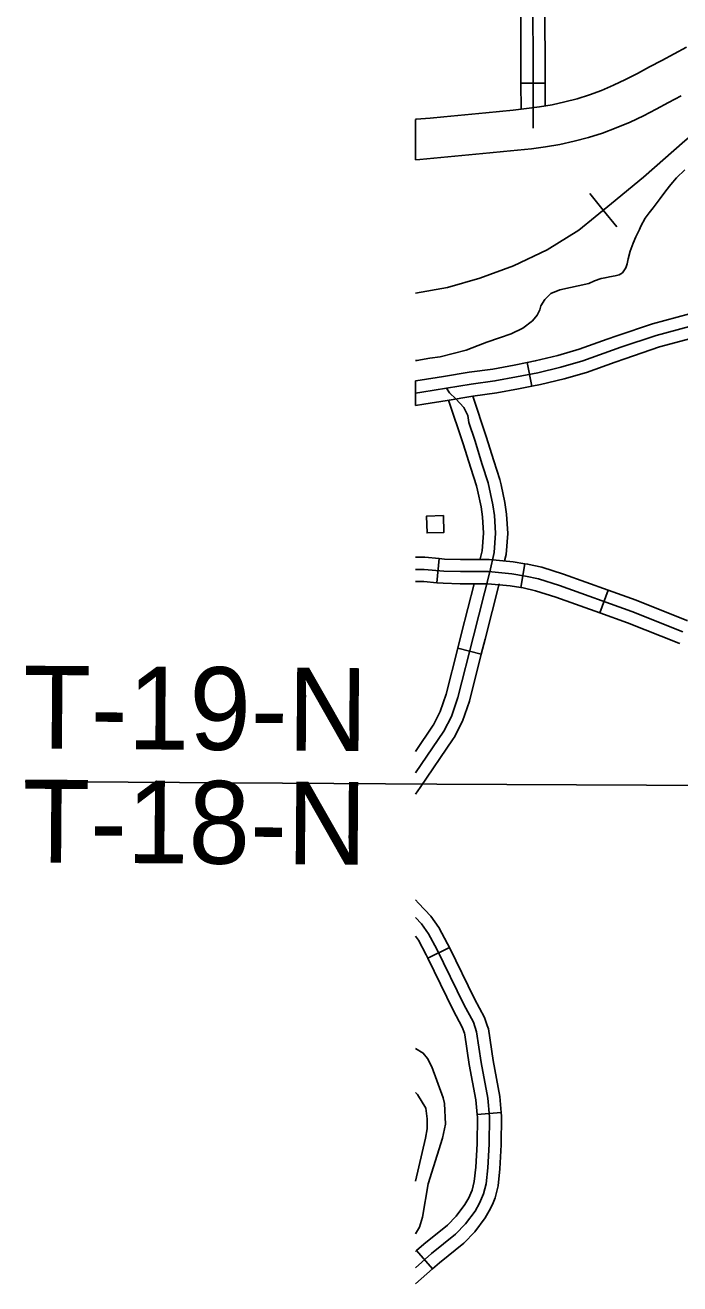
# Model space of a CAD drawing. Extents: x 1370130 to 1380143, y 377636 to 380256.
# Drawn here: x 1377941.5 to 1378111.8, y 378135.3 to 378462.7 of the extents above; entities that cross this region are included whole.
import ezdxf

# ---------------------------------------------------------------- set-up
doc = ezdxf.new("R2010")
doc.units = 0
for name, color, linetype in [('Level 15', 7, 'Continuous'), ('Level 31', 7, 'Continuous'), ('Level 32', 7, 'Continuous'), ('Level 35', 7, 'Continuous'), ('Level 4', 7, 'Continuous'), ('Level 40', 7, 'Continuous'), ('Level 45', 7, 'Continuous'), ('Level 5', 7, 'Continuous'), ('Level 56', 7, 'Continuous'), ('R_Draft', 7, 'Continuous')]:
    doc.layers.add(name, color=color, linetype=linetype)

msp = doc.modelspace()

# ---------------------------------------------------------------- linework, layer by layer
at = {"layer": 'Level 15'}
for p, q in [((1378110.33, 378455.28), (1378107.15, 378453.55)), ((1378113.53, 378457.04), (1378110.33, 378455.28)), ((1378103.99, 378451.84), (1378100.83, 378450.18)), ((1378107.15, 378453.55), (1378103.99, 378451.84)), ((1378097.68, 378448.57), (1378094.58, 378447.07)), ((1378100.83, 378450.18), (1378097.68, 378448.57)), ((1378091.46, 378445.76), (1378088.3, 378444.6)), ((1378094.58, 378447.07), (1378091.46, 378445.76)), ((1378075.35, 378441.45), (1378071.99, 378441.02)), ((1378078.63, 378442.01), (1378075.35, 378441.45)), ((1378081.89, 378442.74), (1378078.63, 378442.01)), ((1378085.11, 378443.59), (1378081.89, 378442.74)), ((1378088.3, 378444.6), (1378085.11, 378443.59)), ((1378105.67, 378440.86), (1378108.93, 378442.58)), ((1378108.93, 378442.58), (1378112.15, 378444.32)), ((1378043.22, 378438.23), (1378043.04, 378438.21)), ((1378043.04, 378438.21), (1378043.04, 378427.66)), ((1378046.85, 378438.56), (1378043.22, 378438.23)), ((1378050.48, 378438.89), (1378046.85, 378438.56)), ((1378054.11, 378439.24), (1378050.48, 378438.89)), ((1378057.75, 378439.59), (1378054.11, 378439.24)), ((1378061.37, 378439.94), (1378057.75, 378439.59)), ((1378064.96, 378440.29), (1378061.37, 378439.94)), ((1378068.51, 378440.65), (1378064.96, 378440.29)), ((1378071.99, 378441.02), (1378068.51, 378440.65)), ((1378098.9, 378437.5), (1378102.35, 378439.17)), ((1378102.35, 378439.17), (1378105.67, 378440.86)), ((1378091.69, 378434.66), (1378095.31, 378435.99)), ((1378095.31, 378435.99), (1378098.9, 378437.5)), ((1378076.91, 378431.06), (1378080.66, 378431.71)), ((1378080.66, 378431.71), (1378084.37, 378432.53)), ((1378084.37, 378432.53), (1378088.04, 378433.51)), ((1378088.04, 378433.51), (1378091.69, 378434.66)), ((1378047.82, 378428.1), (1378051.45, 378428.44)), ((1378051.45, 378428.44), (1378055.12, 378428.78)), ((1378055.12, 378428.78), (1378058.76, 378429.14)), ((1378058.76, 378429.14), (1378062.39, 378429.49)), ((1378062.39, 378429.49), (1378065.99, 378429.85)), ((1378065.99, 378429.85), (1378069.58, 378430.21)), ((1378069.58, 378430.21), (1378073.21, 378430.59)), ((1378073.21, 378430.59), (1378076.91, 378431.06)), ((1378043.04, 378427.66), (1378044.21, 378427.77)), ((1378044.21, 378427.77), (1378047.82, 378428.1))]:
    msp.add_line(p, q, dxfattribs=at)
at = {"layer": 'Level 31'}
for p, q in [((1378063.23, 378373.27), (1378057.08, 378372.42)), ((1378068.72, 378374.29), (1378063.23, 378373.27)), ((1378072.1, 378374.96), (1378068.72, 378374.29)), ((1378073.33, 378368.79), (1378072.1, 378374.96)), ((1378044.25, 378370.35), (1378043.04, 378370.17)), ((1378043.04, 378370.17), (1378043.04, 378363.79)), ((1378050.35, 378371.33), (1378044.25, 378370.35)), ((1378057.08, 378372.42), (1378050.35, 378371.33)), ((1378051.35, 378365.11), (1378058.01, 378366.19)), ((1378058.01, 378366.19), (1378064.23, 378367.05)), ((1378064.23, 378367.05), (1378069.91, 378368.1)), ((1378069.91, 378368.1), (1378073.33, 378368.79)), ((1378043.04, 378363.79), (1378045.23, 378364.13)), ((1378045.23, 378364.13), (1378051.35, 378365.11))]:
    msp.add_line(p, q, dxfattribs=at)
for points in [[(1378043.04, 378366.98), (1378044.74, 378367.24), (1378057.54, 378369.3), (1378063.73, 378370.16), (1378069.32, 378371.2), (1378074.9, 378372.31), (1378080.92, 378373.77), (1378086.59, 378375.41), (1378096.47, 378378.93), (1378105.66, 378382.03), (1378129.47, 378388.39)], [(1378092.93, 378381.01), (1378095.44, 378381.91), (1378104.75, 378385.05), (1378114.36, 378387.61)], [(1378072.1, 378374.96), (1378074.22, 378375.39), (1378080.11, 378376.82), (1378085.62, 378378.41), (1378092.93, 378381.01)], [(1378115.98, 378381.53), (1378106.58, 378379.01), (1378097.5, 378375.96), (1378095.05, 378375.08)], [(1378095.05, 378375.08), (1378087.55, 378372.41), (1378081.73, 378370.73), (1378075.58, 378369.24), (1378073.33, 378368.79)]]:
    msp.add_lwpolyline(points, dxfattribs=at)
at = {"layer": 'Level 32'}
for p, q in [((1378070.51, 378447.63), (1378076.81, 378447.65)), ((1378049.2, 378323.96), (1378048.61, 378317.68)), ((1378071.51, 378322.64), (1378070.5, 378316.42)), ((1378093.17, 378315.77), (1378091.05, 378309.84))]:
    msp.add_line(p, q, dxfattribs=at)
for points in [[(1378101.07, 378492.4), (1378096.28, 378491.2), (1378086.57, 378489.56), (1378080.29, 378489.11), (1378077.9, 378488.51), (1378076.26, 378487.61), (1378075.06, 378486.87), (1378073.87, 378485.52), (1378073.57, 378484.03), (1378073.69, 378435.94)], [(1378070.46, 378469.81), (1378070.51, 378447.63)], [(1378076.76, 378469.83), (1378076.81, 378447.65)], [(1378070.51, 378447.63), (1378070.53, 378440.83)], [(1378076.81, 378447.65), (1378076.83, 378441.64)], [(1378049.2, 378323.96), (1378045.5, 378324.3), (1378043.04, 378324.3)], [(1378071.51, 378322.64), (1378068.5, 378323.13), (1378062.2, 378323.73), (1378054.79, 378323.73), (1378050.62, 378323.82), (1378049.2, 378323.96)], [(1378112.62, 378304.93), (1378099.38, 378310.21), (1378080.57, 378316.93), (1378075.1, 378318.66), (1378071.65, 378319.43), (1378068.1, 378320), (1378062.05, 378320.58), (1378054.76, 378320.58), (1378050.44, 378320.67), (1378045.36, 378321.15), (1378043.04, 378321.15)], [(1378093.17, 378315.77), (1378081.57, 378319.92), (1378075.92, 378321.7), (1378072.24, 378322.52), (1378071.51, 378322.64)], [(1378048.61, 378317.68), (1378045.21, 378318), (1378043.04, 378318)], [(1378070.5, 378316.42), (1378067.69, 378316.88), (1378061.9, 378317.43), (1378054.72, 378317.43), (1378050.26, 378317.53), (1378048.61, 378317.68)], [(1378091.05, 378309.84), (1378079.56, 378313.94), (1378074.28, 378315.61), (1378071.05, 378316.33), (1378070.5, 378316.42)], [(1378113.79, 378307.86), (1378113.69, 378307.89), (1378100.49, 378313.16), (1378093.17, 378315.77)], [(1378111.84, 378301.87), (1378111.54, 378301.97), (1378098.26, 378307.26), (1378091.05, 378309.84)]]:
    msp.add_lwpolyline(points, dxfattribs=at)
at = {"layer": 'Level 35'}
for points in [[(1378113.1, 378425.1), (1378110.98, 378423.02), (1378109.48, 378421.29), (1378108.19, 378419.66), (1378106.7, 378417.59), (1378104.92, 378415.23), (1378103.83, 378413.89), (1378102.82, 378412.52), (1378101.71, 378410.46), (1378101.35, 378409.57), (1378100.4, 378407.65), (1378099.66, 378405.99), (1378098.96, 378403.95), (1378098.39, 378401.95), (1378098.1, 378400.6), (1378097.79, 378399.58), (1378096.9, 378398.33), (1378096.08, 378397.8), (1378095, 378397.48), (1378093.5, 378397.22), (1378092.41, 378397.02), (1378091.41, 378396.82), (1378089.67, 378396.22), (1378088.14, 378395.51), (1378080.61, 378393.91)], [(1378080.61, 378393.91), (1378078.25, 378392.89), (1378076.7, 378391.38), (1378075.7, 378389.75), (1378075.4, 378388.69), (1378074.76, 378387.32), (1378073.47, 378385.85), (1378070.97, 378383.89), (1378067.95, 378382.41), (1378064.92, 378381.39), (1378061.6, 378380.24), (1378059.4, 378379.38), (1378056.25, 378378.19), (1378049.5, 378376.47), (1378046.83, 378376.06), (1378043.45, 378375.49), (1378043.04, 378375.45)], [(1378043.04, 378148.27), (1378044.15, 378150.07), (1378044.9, 378152.61), (1378046.37, 378161.31), (1378050.13, 378173.22), (1378050.86, 378176.85), (1378050.58, 378182.24), (1378050.3, 378183.7), (1378047.31, 378191.76), (1378046.17, 378193.93), (1378045.09, 378195.34), (1378043.04, 378196.5)], [(1378043.04, 378162.04), (1378045.71, 378173.17), (1378046.08, 378175.62), (1378046.15, 378178.27), (1378045.76, 378181), (1378043.58, 378184.53), (1378043.04, 378185.12)]]:
    msp.add_lwpolyline(points, dxfattribs=at)
at = {"layer": 'Level 4'}
msp.add_lwpolyline([(1378139.53, 378264.86), (1378048.6, 378265.32)], dxfattribs=at)
at = {"layer": 'Level 40'}
for q in [(1378088.4, 378418.89), (1378095.41, 378410.3)]:
    msp.add_line((1378091.9, 378414.59), q, dxfattribs=at)
for points in [[(1378165.23, 378452.45), (1378160.72, 378452.54), (1378156.77, 378452.45), (1378152.55, 378452.17), (1378146.85, 378450.98), (1378137.2, 378448.22), (1378131.23, 378445.65), (1378126.18, 378442.8), (1378121.49, 378439.58), (1378113.13, 378432.59), (1378102.38, 378423.21), (1378094.02, 378416.32), (1378085.56, 378409.42), (1378077.29, 378404.28), (1378068.57, 378400.14), (1378059.84, 378396.92), (1378051.38, 378394.44), (1378043.04, 378393)], [(1378113.13, 378432.59), (1378102.38, 378423.21), (1378094.02, 378416.32), (1378085.56, 378409.42), (1378077.29, 378404.28), (1378068.57, 378400.14), (1378059.84, 378396.92), (1378051.38, 378394.44), (1378043.04, 378393)]]:
    msp.add_lwpolyline(points, dxfattribs=at)
at = {"layer": 'Level 45'}
for p, q in [((1378060.19, 378299.09), (1378054.08, 378300.62)), ((1378051.91, 378222.81), (1378046.25, 378220.04)), ((1378065.38, 378179.9), (1378059.11, 378179.34)), ((1378047.51, 378139.22), (1378043.36, 378143.96))]:
    msp.add_line(p, q, dxfattribs=at)
for points in [[(1378062.41, 378320.54), (1378063.51, 378325.51), (1378063.93, 378330.55), (1378063.65, 378335.17), (1378063.23, 378337.97), (1378061.98, 378343.71), (1378060.44, 378348.47), (1378058.48, 378354.77), (1378056.94, 378359.38), (1378056.66, 378361.2), (1378055.68, 378363.3), (1378053.58, 378365.54), (1378051.9, 378367.08), (1378051.1, 378368.26)], [(1378065.33, 378343.11), (1378065.02, 378344.53), (1378063.44, 378349.42), (1378061.48, 378355.73), (1378057.99, 378366.19)], [(1378059.18, 378341.76), (1378058.93, 378342.88), (1378057.43, 378347.52), (1378055.48, 378353.8), (1378051.69, 378365.17)], [(1378059.94, 378323.94), (1378060.39, 378325.99), (1378060.78, 378330.59), (1378060.52, 378334.84), (1378060.14, 378337.4), (1378059.18, 378341.76)], [(1378066.26, 378323.34), (1378066.64, 378325.04), (1378067.09, 378330.52), (1378066.79, 378335.5), (1378066.33, 378338.54), (1378065.33, 378343.11)], [(1378043.04, 378268.19), (1378050.43, 378279.07), (1378052.4, 378282.92), (1378054.11, 378287.8), (1378058.13, 378303.8), (1378062.41, 378320.54)], [(1378054.08, 378300.62), (1378055.07, 378304.57), (1378058.36, 378317.43)], [(1378060.19, 378299.09), (1378061.18, 378303.03), (1378064.86, 378317.43)], [(1378047.68, 378280.63), (1378047.72, 378280.68), (1378049.5, 378284.16), (1378051.09, 378288.71), (1378054.08, 378300.62)], [(1378052.89, 378277.09), (1378053.15, 378277.46), (1378055.3, 378281.68), (1378057.13, 378286.89), (1378060.19, 378299.09)], [(1378043.04, 378273.8), (1378047.68, 378280.63)], [(1378043.04, 378262.72), (1378044.28, 378264.42), (1378052.89, 378277.09)], [(1378051.91, 378222.81), (1378051.44, 378223.77), (1378049.17, 378228.04), (1378047.05, 378230.93), (1378043.9, 378234.36), (1378043.04, 378235.22)], [(1378043.04, 378139.49), (1378047.27, 378143.19), (1378053.51, 378148.24), (1378056.08, 378150.89), (1378058.56, 378154.23), (1378059.75, 378156.28), (1378060.78, 378158.68), (1378061.46, 378161.33), (1378061.89, 378165.44), (1378062.23, 378171.6), (1378062.32, 378178.79), (1378061.89, 378183.58), (1378060.18, 378192.9), (1378058.98, 378200.86), (1378058.13, 378203.34), (1378055.65, 378207.96), (1378048.64, 378222.34), (1378046.5, 378226.36), (1378044.62, 378228.93), (1378043.04, 378230.64)], [(1378046.25, 378220.04), (1378045.83, 378220.91), (1378043.82, 378224.68), (1378043.04, 378225.75)], [(1378061.74, 378202.52), (1378061.02, 378204.61), (1378058.45, 378209.4), (1378051.91, 378222.81)], [(1378055.79, 378200.47), (1378055.23, 378202.08), (1378052.84, 378206.53), (1378046.25, 378220.04)], [(1378065.38, 378179.9), (1378065.02, 378184), (1378063.29, 378193.42), (1378062.06, 378201.62), (1378061.74, 378202.52)], [(1378059.11, 378179.34), (1378058.77, 378183.15), (1378057.07, 378192.39), (1378055.91, 378200.11), (1378055.79, 378200.47)], [(1378063.24, 378156.41), (1378063.77, 378157.66), (1378064.57, 378160.77), (1378065.03, 378165.19), (1378065.38, 378171.49), (1378065.47, 378178.91), (1378065.38, 378179.9)], [(1378057.44, 378158.89), (1378057.79, 378159.7), (1378058.35, 378161.89), (1378058.75, 378165.69), (1378059.08, 378171.7), (1378059.17, 378178.66), (1378059.11, 378179.34)], [(1378043.36, 378143.96), (1378045.24, 378145.6), (1378051.38, 378150.57), (1378053.67, 378152.93), (1378055.92, 378155.97), (1378056.93, 378157.7), (1378057.44, 378158.89)], [(1378047.51, 378139.22), (1378049.29, 378140.78), (1378055.64, 378145.91), (1378058.48, 378148.85), (1378061.19, 378152.49), (1378062.57, 378154.86), (1378063.24, 378156.41)], [(1378043.04, 378143.68), (1378043.36, 378143.96)], [(1378043.04, 378135.31), (1378047.51, 378139.22)]]:
    msp.add_lwpolyline(points, dxfattribs=at)
at = {"layer": 'Level 5'}
msp.add_lwpolyline([(1378048.6, 378265.32), (1377941.57, 378266)], dxfattribs=at)
at = {"layer": 'Level 56'}
msp.add_lwpolyline([(1378050.34, 378335.15), (1378050.48, 378330.78), (1378046.1, 378330.64), (1378045.96, 378335.01)], close=True, dxfattribs=at)

# ---------------------------------------------------------------- texts
at = {"layer": 'R_Draft'}
for s, p in [('T-19-N', (1377940.97, 378274.57)), ('T-18-N', (1377940.75, 378244.96))]:
    msp.add_text(s, height=21.538, rotation=359.5722, dxfattribs=at).set_placement(p)

doc.saveas('drawing.dxf')
